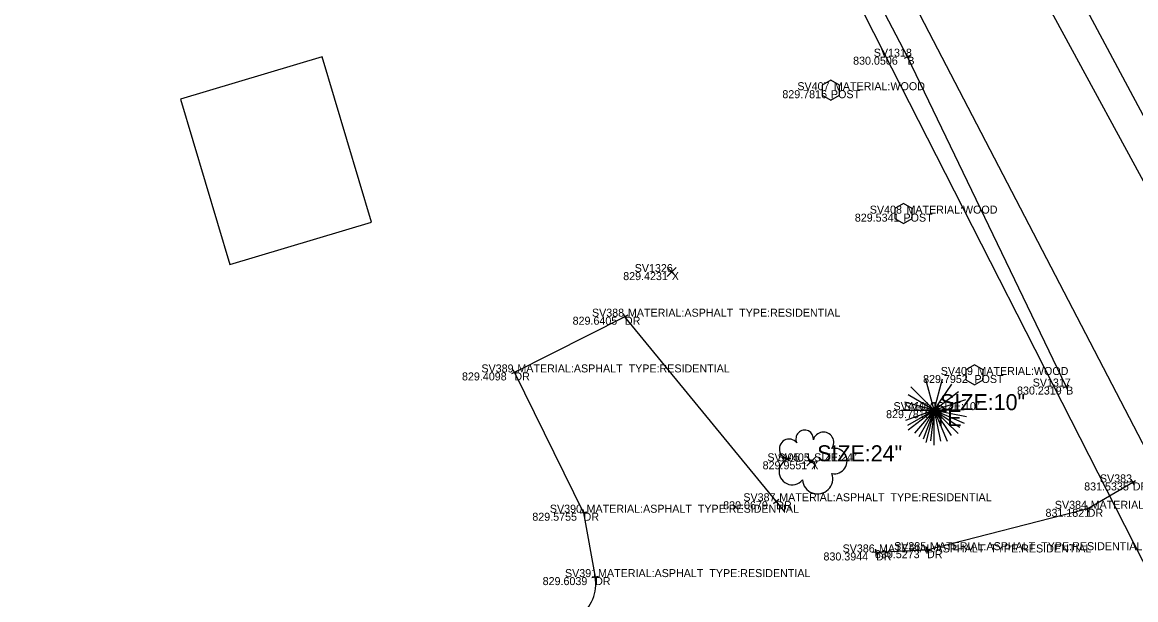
# Model space of a CAD drawing. Extents: x 1715717 to 1717046, y 393954 to 396000.
# Drawn here: x 1716038.3 to 1716121.8, y 394873.9 to 394917.2 of the extents above; entities that cross this region are included whole.
import ezdxf

# ---------------------------------------------------------------- set-up
doc = ezdxf.new("R2010")
doc.units = 0
for name, color, linetype in [('BD_X_Building', 7, 'Continuous'), ('PV_X_Driveway', 7, 'Continuous'), ('PV_X_EOP', 7, 'Continuous'), ('PV_X_Shoulder', 7, 'Continuous'), ('RD_X_Cells', 7, 'Continuous'), ('SV_X_Break_Lines', 7, 'Continuous'), ('SV_X_Random_Point', 7, 'Continuous'), ('SV_X_Shot_Marker', 7, 'Continuous'), ('SV_X_Text_Comment', 7, 'Continuous'), ('SV_X_Text_Description', 7, 'Continuous'), ('SV_X_Text_Elevation', 7, 'Continuous'), ('SV_X_Text_Name', 7, 'Continuous'), ('UT_X_Overhead_Telecom', 7, 'Continuous'), ('UT_X_Water', 7, 'Continuous'), ('VG_X_Cells', 7, 'Continuous'), ('VG_X_Text', 7, 'Continuous')]:
    doc.layers.add(name, color=color, linetype=linetype)

msp = doc.modelspace()

# ---------------------------------------------------------------- linework, layer by layer
at = {"layer": 'BD_X_Building'}
msp.add_lwpolyline([(1716064.485, 394902.24), (1716060.783, 394914.628), (1716050.175, 394911.459), (1716053.877, 394899.07)], close=True, dxfattribs=at)
at = {"layer": 'PV_X_Driveway'}
for p, q in [((1716083.483, 394895.148), (1716075.198, 394890.971)), ((1716094.823, 394881.313), (1716083.483, 394895.148)), ((1716075.198, 394890.971), (1716080.384, 394880.453)), ((1716121.542, 394882.724), (1716118.161, 394880.747)), ((1716095.473, 394880.519), (1716094.823, 394881.313)), ((1716080.384, 394880.453), (1716081.246, 394875.627)), ((1716118.161, 394880.747), (1716106.118, 394877.646)), ((1716106.118, 394877.646), (1716102.298, 394877.475))]:
    msp.add_line(p, q, dxfattribs=at)
msp.add_arc((1716078.313, 394875.103), 2.979, 305.24906, 10.1308, dxfattribs=at)
at = {"layer": 'PV_X_EOP'}
msp.add_lwpolyline([(1716192.806, 394770.884), (1716180.242, 394796.041), (1716167.628, 394820.845), (1716155.004, 394845.287), (1716145.506, 394863.821), (1716141.346, 394866.867), (1716134.052, 394880.91), (1716128.147, 394893.321), (1716126.682, 394902.088), (1716113.574, 394926.636), (1716101.445, 394949.877), (1716087.273, 394977.198), (1716074.505, 395002.018), (1716061.029, 395028.016), (1716048.685, 395053.532), (1716035.735, 395078.371), (1716022.413, 395104.586), (1716008.497, 395130.494), (1715995.097, 395157.625), (1715982.198, 395182.92), (1715969.659, 395207.322), (1715955.111, 395234.904), (1715953.572, 395236.657), (1715945.123, 395249.034)], dxfattribs=at)
at = {"layer": 'PV_X_Shoulder'}
msp.add_lwpolyline([(1715949.233, 395241.374), (1715962.901, 395217.167), (1715975.906, 395192.159), (1715987.602, 395167.635), (1715999.35, 395143.392), (1716012.228, 395119.063), (1716024.465, 395094.804), (1716037.27, 395069.747), (1716050.194, 395045.906), (1716062.529, 395021.767), (1716075.327, 394996.279), (1716087.31, 394972.406), (1716100.487, 394947.355), (1716113.392, 394921.79), (1716125.614, 394899.264)], dxfattribs=at)
at = {"layer": 'RD_X_Cells'}
for points in [[(1716098.273, 394911.754), (1716098.922, 394911.379), (1716099.571, 394911.754), (1716099.571, 394912.504), (1716098.922, 394912.879), (1716098.273, 394912.504), (1716098.273, 394911.754)], [(1716103.709, 394902.501), (1716104.358, 394902.126), (1716105.007, 394902.501), (1716105.007, 394903.251), (1716104.358, 394903.626), (1716103.709, 394903.251), (1716103.709, 394902.501)], [(1716109.025, 394890.405), (1716109.674, 394890.03), (1716110.323, 394890.405), (1716110.323, 394891.155), (1716109.674, 394891.53), (1716109.025, 394891.155), (1716109.025, 394890.405)]]:
    msp.add_lwpolyline(points, dxfattribs=at)
at = {"layer": 'SV_X_Break_Lines'}
msp.add_lwpolyline([(1716116.552, 394889.913), (1716104.65, 394914.641), (1716092.251, 394938.392), (1716077.588, 394958.783)], dxfattribs=at)
at = {"layer": 'SV_X_Random_Point'}
for p, q in [((1716086.659, 394898.158), (1716087.325, 394898.826)), ((1716086.659, 394898.826), (1716087.325, 394898.158)), ((1716106.329, 394887.809), (1716106.996, 394888.477)), ((1716106.329, 394888.477), (1716106.996, 394887.809)), ((1716097.111, 394883.975), (1716097.778, 394884.642)), ((1716097.111, 394884.642), (1716097.778, 394883.975))]:
    msp.add_line(p, q, dxfattribs=at)
at = {"layer": 'SV_X_Shot_Marker'}
for p, q in [((1716104.425, 394914.533), (1716104.875, 394914.75)), ((1716104.758, 394914.416), (1716104.541, 394914.866)), ((1716104.65, 394914.641), (1716104.65, 394914.641)), ((1716083.706, 394895.261), (1716083.259, 394895.036)), ((1716083.595, 394894.925), (1716083.37, 394895.371)), ((1716083.483, 394895.148), (1716083.483, 394895.148)), ((1716075.422, 394891.081), (1716074.974, 394890.86)), ((1716075.087, 394891.195), (1716075.308, 394890.746)), ((1716075.198, 394890.971), (1716075.198, 394890.971)), ((1716116.327, 394889.804), (1716116.778, 394890.021)), ((1716116.661, 394889.688), (1716116.444, 394890.138)), ((1716116.552, 394889.913), (1716116.552, 394889.913)), ((1716121.668, 394882.508), (1716121.416, 394882.94)), ((1716121.758, 394882.85), (1716121.326, 394882.598)), ((1716121.542, 394882.724), (1716121.542, 394882.724)), ((1716094.629, 394881.155), (1716095.016, 394881.471)), ((1716094.981, 394881.12), (1716094.664, 394881.506)), ((1716094.823, 394881.313), (1716094.823, 394881.313)), ((1716080.63, 394880.496), (1716080.138, 394880.409)), ((1716080.34, 394880.699), (1716080.428, 394880.206)), ((1716080.384, 394880.453), (1716080.384, 394880.453)), ((1716118.403, 394880.809), (1716117.919, 394880.685)), ((1716118.223, 394880.505), (1716118.099, 394880.989)), ((1716118.161, 394880.747), (1716118.161, 394880.747)), ((1716102.548, 394877.486), (1716102.048, 394877.463)), ((1716102.309, 394877.225), (1716102.287, 394877.724)), ((1716102.298, 394877.475), (1716102.298, 394877.475)), ((1716106.367, 394877.658), (1716105.868, 394877.635)), ((1716106.129, 394877.397), (1716106.106, 394877.896)), ((1716106.118, 394877.646), (1716106.118, 394877.646)), ((1716081.492, 394875.671), (1716081, 394875.584)), ((1716081.202, 394875.874), (1716081.29, 394875.381)), ((1716081.246, 394875.627), (1716081.246, 394875.627))]:
    msp.add_line(p, q, dxfattribs=at)
at = {"layer": 'UT_X_Overhead_Telecom'}
msp.add_line((1716209.528, 394705.313), (1716026.851, 395064.482), dxfattribs=at)
at = {"layer": 'UT_X_Water'}
msp.add_lwpolyline([(1716175.851, 394782.59), (1716103.993, 394920.906), (1716033.667, 394991.804)], dxfattribs=at)
at = {"layer": 'VG_X_Cells'}
for p, q in [((1716106.662, 394888.143), (1716106.045, 394890.45)), ((1716106.662, 394888.143), (1716107.291, 394890.492)), ((1716106.662, 394888.143), (1716104.917, 394889.886)), ((1716106.662, 394888.143), (1716107.99, 394890.085)), ((1716106.662, 394888.143), (1716104.709, 394889.291)), ((1716106.662, 394888.143), (1716108.491, 394889.545)), ((1716106.662, 394888.143), (1716109.031, 394888.946)), ((1716104.195, 394888.143), (1716106.662, 394888.143)), ((1716106.662, 394888.143), (1716104.456, 394888.735)), ((1716106.662, 394888.143), (1716104.517, 394887.362)), ((1716106.662, 394888.143), (1716104.671, 394887.002)), ((1716106.662, 394888.143), (1716104.709, 394886.645)), ((1716106.662, 394888.143), (1716105.19, 394886.41)), ((1716106.662, 394888.143), (1716105.503, 394886.135)), ((1716106.662, 394888.143), (1716105.83, 394885.973)), ((1716106.662, 394888.143), (1716106.031, 394885.715)), ((1716106.662, 394888.143), (1716106.392, 394885.847)), ((1716106.662, 394888.143), (1716108.917, 394888.189)), ((1716106.662, 394885.523), (1716106.662, 394888.143)), ((1716106.662, 394888.143), (1716107.123, 394885.825)), ((1716106.662, 394888.143), (1716107.629, 394885.809)), ((1716106.662, 394888.143), (1716107.931, 394886.246)), ((1716106.662, 394888.143), (1716108.457, 394886.382)), ((1716106.662, 394888.143), (1716108.573, 394886.865)), ((1716106.662, 394888.143), (1716108.895, 394887.172)), ((1716106.662, 394888.143), (1716109.077, 394887.664))]:
    msp.add_line(p, q, dxfattribs=at)
msp.add_circle((1716097.445, 394884.309), 0.12, dxfattribs=at)
for centre, radius, start, end in [((1716096.953, 394885.992), 0.658, 354.0047, 205.97412), ((1716098.358, 394885.723), 0.776, 323.82996, 165.0376), ((1716095.79, 394885.241), 0.735, 39.06254, 279.54124), ((1716099.175, 394884.327), 0.957, 259.14531, 101.45961), ((1716096.018, 394883.534), 0.987, 96.17219, 320.57371), ((1716097.918, 394883.006), 1.142, 184.94757, 19.45715)]:
    msp.add_arc(centre, radius, start, end, dxfattribs=at)

# ---------------------------------------------------------------- texts
at = {"layer": 'SV_X_Text_Comment'}
for s, height, p in [('B', 0.6, (1716104.65, 394914.041)), ('POST', 0.6, (1716098.922, 394911.529)), ('POST', 0.6, (1716104.358, 394902.276)), ('X', 0.6, (1716086.992, 394897.892)), ('DR', 0.6, (1716083.483, 394894.548)), ('DR', 0.6, (1716075.198, 394890.371)), ('POST', 0.6, (1716109.674, 394890.18)), ('B', 0.6, (1716116.552, 394889.313)), ('X', 0.6, (1716106.662, 394887.543)), ('TE', 1.2, (1716106.662, 394886.943)), ('T', 0.6, (1716097.445, 394883.709)), ('X', 0.6, (1716097.445, 394883.709)), ('DR', 0.6, (1716121.542, 394882.124)), ('DR', 0.6, (1716094.823, 394880.713)), ('DR', 0.6, (1716080.384, 394879.852)), ('DR', 0.6, (1716118.161, 394880.147)), ('DR', 0.6, (1716102.298, 394876.875)), ('DR', 0.6, (1716106.118, 394877.046)), ('DR', 0.6, (1716081.246, 394875.027))]:
    msp.add_text(s, height=height, dxfattribs=at).set_placement(p)
at = {"layer": 'SV_X_Text_Description'}
for s, p in [(' MATERIAL:WOOD ', (1716098.922, 394912.129)), (' MATERIAL:WOOD ', (1716104.358, 394902.876)), (' MATERIAL:ASPHALT  TYPE:RESIDENTIAL ', (1716083.483, 394895.148)), (' MATERIAL:ASPHALT  TYPE:RESIDENTIAL ', (1716075.198, 394890.971)), (' MATERIAL:WOOD ', (1716109.674, 394890.78)), (' SIZE:10" ', (1716106.662, 394888.143)), (' SIZE:24" ', (1716097.445, 394884.309)), (' MATERIAL:ASPHALT  TYPE:RESIDENTIAL ', (1716094.823, 394881.313)), (' MATERIAL:ASPHALT  TYPE:RESIDENTIAL ', (1716118.161, 394880.747)), (' MATERIAL:ASPHALT  TYPE:RESIDENTIAL ', (1716080.384, 394880.453)), (' MATERIAL:ASPHALT  TYPE:RESIDENTIAL ', (1716102.298, 394877.475)), (' MATERIAL:ASPHALT  TYPE:RESIDENTIAL ', (1716106.118, 394877.646)), (' MATERIAL:ASPHALT  TYPE:RESIDENTIAL ', (1716081.246, 394875.627))]:
    msp.add_text(s, height=0.6, dxfattribs=at).set_placement(p)
at = {"layer": 'SV_X_Text_Elevation'}
for s, p in [('830.0506', (1716100.582, 394914.041)), ('829.7816', (1716095.28, 394911.529)), ('829.5341', (1716100.711, 394902.276)), ('829.4231', (1716083.354, 394897.892)), ('829.6405', (1716079.562, 394894.548)), ('829.4098', (1716071.272, 394890.371)), ('829.7952', (1716105.828, 394890.18)), ('830.2319', (1716112.868, 394889.313)), ('829.7819', (1716103.053, 394887.543)), ('829.7819', (1716103.053, 394887.543)), ('829.9551', (1716093.802, 394883.709)), ('829.9551', (1716093.802, 394883.709)), ('831.5335', (1716117.9, 394882.124)), ('830.0679', (1716090.845, 394880.713)), ('829.5755', (1716076.543, 394879.852)), ('831.1821', (1716115.001, 394880.147)), ('830.3944', (1716098.363, 394876.875)), ('830.5273', (1716102.22, 394877.046)), ('829.6039', (1716077.316, 394875.027))]:
    msp.add_text(s, height=0.6, dxfattribs=at).set_placement(p)
at = {"layer": 'SV_X_Text_Name'}
for s, p in [('SV1318', (1716102.132, 394914.641)), ('SV407', (1716096.404, 394912.129)), ('SV408', (1716101.835, 394902.876)), ('SV1326', (1716084.214, 394898.492)), ('SV388', (1716081.012, 394895.148)), ('SV389', (1716072.727, 394890.971)), ('SV409', (1716107.151, 394890.78)), ('SV1317', (1716114.04, 394889.913)), ('SV410_1', (1716103.611, 394888.143)), ('SV410', (1716104.386, 394888.143)), ('SV405_1', (1716094.157, 394884.309)), ('SV405', (1716094.927, 394884.309)), ('SV383', (1716119.076, 394882.724)), ('SV387', (1716092.357, 394881.313)), ('SV384', (1716115.7, 394880.747)), ('SV390', (1716077.857, 394880.453)), ('SV386', (1716099.794, 394877.475)), ('SV385', (1716103.652, 394877.646)), ('SV391', (1716078.988, 394875.627))]:
    msp.add_text(s, height=0.6, dxfattribs=at).set_placement(p)
at = {"layer": 'VG_X_Text'}
for s, p in [(' SIZE:10" ', (1716106.662, 394888.143)), (' SIZE:24" ', (1716097.445, 394884.309))]:
    msp.add_text(s, height=1.2, dxfattribs=at).set_placement(p)

doc.saveas('drawing.dxf')
